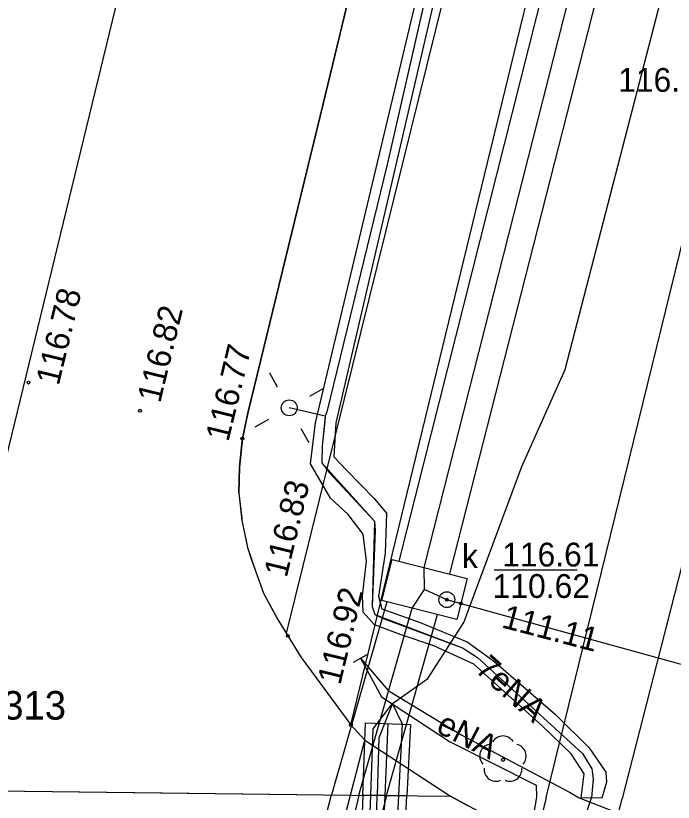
# Model space of a CAD drawing. Extents: x 6424617 to 6425697, y 5665845 to 5667190.
# Drawn here: x 6425408.09 to 6425428.81, y 5666563.12 to 5666587.89 of the extents above; entities that cross this region are included whole.
import ezdxf

# ---------------------------------------------------------------- set-up
doc = ezdxf.new("R2010")
doc.units = 0
for name, color, linetype in [('Warstwa 10', 7, 'Continuous'), ('Warstwa 11', 7, 'Continuous'), ('Warstwa 12', 7, 'Continuous'), ('Warstwa 13', 7, 'Continuous'), ('Warstwa 14', 7, 'Continuous'), ('Warstwa 15', 7, 'Continuous'), ('Warstwa 16', 7, 'Continuous'), ('Warstwa 2', 7, 'Continuous'), ('Warstwa 20', 7, 'Continuous'), ('Warstwa 25', 7, 'Continuous'), ('Warstwa 4', 7, 'Continuous'), ('Warstwa 5', 7, 'Continuous'), ('Warstwa 6', 7, 'Continuous'), ('Warstwa 61', 7, 'Continuous'), ('Warstwa 8', 7, 'Continuous'), ('Warstwa 9', 7, 'Continuous')]:
    doc.layers.add(name, color=color, linetype=linetype)

msp = doc.modelspace()

# ---------------------------------------------------------------- linework, layer by layer
at = {"layer": 'Warstwa 10'}
for points in [[(6425463.69, 5666713.42), (6425450.198, 5666658.334), (6425446.682, 5666643.647), (6425444.432, 5666634.297), (6425443.938, 5666632.196), (6425440.201, 5666616.58), (6425435.586, 5666597.316), (6425432.855, 5666585.915), (6425430.384, 5666576.151), (6425429.068, 5666570.528), (6425427.199, 5666563.24)], [(6425408.526, 5666486.136), (6425415.189, 5666513.682), (6425415.8, 5666514.595), (6425416.059, 5666515.322), (6425416.046, 5666515.972), (6425415.903, 5666516.524), (6425415.527, 5666516.858), (6425414.977, 5666516.815), (6425414.617, 5666516.009), (6425414.558, 5666515.29), (6425414.733, 5666514.858), (6425415.232, 5666514.782), (6425415.536, 5666515.098), (6425427.199, 5666563.24)]]:
    msp.add_lwpolyline(points, dxfattribs=at)
at = {"layer": 'Warstwa 11'}
msp.add_circle((6425423.441, 5666564.454), 0.05, dxfattribs=at)
for centre, start, end in [((6425423.441, 5666564.829), 30.1471, 149.8529), ((6425423.084, 5666564.57), 102.1471, 221.8529), ((6425423.798, 5666564.57), 318.1471, 77.8529), ((6425423.221, 5666564.151), 174.1471, 293.8529), ((6425423.661, 5666564.151), 246.1471, 5.8529)]:
    msp.add_arc(centre, 0.375, start, end, dxfattribs=at)
at = {"layer": 'Warstwa 12'}
for points in [[(6425429.948, 5666625.73), (6425423.857, 5666601.014), (6425423.825, 5666600.868), (6425423.805, 5666600.77), (6425423.785, 5666600.674), (6425419.792, 5666583.207), (6425417.89, 5666575.411), (6425417.843, 5666575.274), (6425417.83, 5666575.116), (6425417.74, 5666574.332), (6425417.734, 5666573.808), (6425417.958, 5666573.509), (6425419.396, 5666571.967), (6425419.414, 5666571.671), (6425419.317, 5666569.282), (6425419.405, 5666569.031), (6425419.7, 5666568.897), (6425422.168, 5666567.979), (6425422.642, 5666567.678), (6425425.95, 5666564.655), (6425426.241, 5666564.174), (6425426.282, 5666563.854), (6425426.235, 5666563.252)], [(6425419.959, 5666566.232), (6425421.072, 5666567.014), (6425422.209, 5666568.78), (6425424.038, 5666573.694), (6425425.402, 5666576.749), (6425429.473, 5666592.484), (6425433.587, 5666608.959), (6425433.509, 5666609.712), (6425433.806, 5666610.423), (6425435.93, 5666619.047)], [(6425432.007, 5666617.006), (6425426.287, 5666594.949), (6425420.155, 5666570.71)], [(6425421.765, 5666570.306), (6425427.85, 5666594.158), (6425433.674, 5666616.636)], [(6425424.798, 5666563.269), (6425430.321, 5666585.708), (6425436.792, 5666612.249), (6425437.109, 5666613.288)], [(6425417.843, 5666575.274), (6425416.706, 5666575.54)], [(6425441.217, 5666568.14), (6425439.239, 5666564.653), (6425421.672, 5666569.496), (6425420.968, 5666569.82)], [(6425419.785, 5666569.432), (6425418.038, 5666563.351)], [(6425419.768, 5666563.33), (6425421.383, 5666569.03)], [(6425418.947, 5666567.651), (6425419.614, 5666566.433), (6425421.76, 5666565.033), (6425424.489, 5666563.655), (6425424.494, 5666563.273)], [(6425418.947, 5666567.651), (6425419.822, 5666566.636), (6425422.142, 5666565.233), (6425425.539, 5666563.437), (6425425.841, 5666563.257)], [(6425419.277, 5666563.335), (6425419.354, 5666565.433), (6425419.959, 5666566.232)], [(6425419.959, 5666566.232), (6425419.526, 5666565.15), (6425419.478, 5666563.333)], [(6425420.158, 5666563.325), (6425420.274, 5666565.579), (6425419.959, 5666566.232)], [(6425407.053, 5666520.958), (6425418.038, 5666563.351)], [(6425419.768, 5666563.33), (6425408.806, 5666520.576)], [(6425419.239, 5666554.223), (6425418.943, 5666554.234), (6425419.277, 5666563.335)], [(6425419.239, 5666554.223), (6425419.478, 5666563.333)], [(6425419.239, 5666554.223), (6425419.689, 5666554.213), (6425420.158, 5666563.325)], [(6425424.798, 5666563.269), (6425407.429, 5666491.384), (6425382.182, 5666389.031), (6425381.68, 5666386.39)], [(6425424.494, 5666563.273), (6425422.467, 5666551.627), (6425413.972, 5666545.439), (6425413.323, 5666547.257)], [(6425414.219, 5666544.781), (6425422.911, 5666551.121), (6425426.036, 5666562.658), (6425426.235, 5666563.252)], [(6425425.841, 5666563.257), (6425426.893, 5666562.844), (6425427.082, 5666562.782), (6425427.381, 5666562.688), (6425427.779, 5666562.543), (6425429.234, 5666562.096)]]:
    msp.add_lwpolyline(points, dxfattribs=at)
at = {"layer": 'Warstwa 14'}
msp.add_lwpolyline([(6425425.777, 5666570.426), (6425423.161, 5666570.426)], dxfattribs=at)
for centre in [(6425421.672, 5666569.496), (6425422.114, 5666569.374)]:
    msp.add_circle(centre, 0.045, dxfattribs=at)
at = {"layer": 'Warstwa 16'}
msp.add_lwpolyline([(6425419.946, 5666570.763), (6425422.313, 5666570.168), (6425421.989, 5666568.877), (6425419.622, 5666569.473)], close=True, dxfattribs=at)
at = {"layer": 'Warstwa 2'}
msp.add_circle((6425416.706, 5666575.54), 0.25, dxfattribs=at)
at = {"layer": 'Warstwa 20'}
msp.add_line((6425418.729, 5666567.528), (6425419.165, 5666567.774), dxfattribs=at)
at = {"layer": 'Warstwa 25'}
for centre in [(6425408.486, 5666576.334), (6425412.001, 5666575.449), (6425415.23, 5666574.57), (6425416.66, 5666568.36), (6425418.65, 5666565.55)]:
    msp.add_circle(centre, 0.045, dxfattribs=at)
at = {"layer": 'Warstwa 4'}
for points in [[(6425416.337, 5666576.193), (6425416.091, 5666576.628)], [(6425417.359, 5666575.909), (6425417.794, 5666576.155)], [(6425416.053, 5666575.171), (6425415.618, 5666574.925)], [(6425417.075, 5666574.887), (6425417.321, 5666574.452)]]:
    msp.add_lwpolyline(points, dxfattribs=at)
msp.add_circle((6425421.672, 5666569.496), 0.25, dxfattribs=at)
at = {"layer": 'Warstwa 6'}
for points in [[(6425428.85, 5666619.55), (6425426.7, 5666617.43), (6425424.86, 5666613.84), (6425424.28, 5666611.91), (6425421.77, 5666601.61), (6425418.68, 5666588.86), (6425417.78, 5666585.11), (6425415.4, 5666575.37), (6425415.23, 5666574.57), (6425415.135, 5666573.675), (6425415.12, 5666572.85), (6425415.215, 5666571.993), (6425415.386, 5666571.143), (6425415.65, 5666570.37), (6425415.897, 5666569.705), (6425416.353, 5666568.851), (6425416.66, 5666568.36), (6425417.08, 5666567.68), (6425418.65, 5666565.55), (6425419.09, 5666565.07), (6425421.792, 5666563.306)], [(6425456.703, 5666531.501), (6425459.304, 5666543.782), (6425462.987, 5666543.257), (6425466.579, 5666542.746), (6425468.099, 5666550.832), (6425426.818, 5666561.105), (6425426.239, 5666561.299), (6425425.664, 5666561.506), (6425425.094, 5666561.725), (6425424.53, 5666561.957), (6425423.97, 5666562.202), (6425423.417, 5666562.46), (6425422.869, 5666562.73), (6425422.328, 5666563.012), (6425421.793, 5666563.306)]]:
    msp.add_lwpolyline(points, dxfattribs=at)
at = {"layer": 'Warstwa 61'}
for points in [[(6425475.759, 5666812.66), (6425466.898, 5666777.865), (6425461.33, 5666753.166), (6425457.929, 5666738.982), (6425455.155, 5666727.822), (6425448.977, 5666702.201), (6425442.987, 5666677.871), (6425436.476, 5666651.999), (6425429.948, 5666625.73), (6425423.857, 5666601.014), (6425419.792, 5666583.207), (6425417.89, 5666575.411), (6425417.843, 5666575.274), (6425417.74, 5666574.332), (6425417.734, 5666573.808), (6425419.396, 5666571.967), (6425419.317, 5666569.282), (6425419.405, 5666569.031), (6425422.168, 5666567.979), (6425422.642, 5666567.678), (6425425.95, 5666564.655), (6425426.241, 5666564.174), (6425426.282, 5666563.854), (6425426.235, 5666563.252)], [(6425418.903, 5666563.341), (6425418.966, 5666563.56), (6425420.584, 5666569.231), (6425420.968, 5666569.82), (6425420.96, 5666570.508), (6425427.069, 5666594.554), (6425432.841, 5666616.822), (6425433.006, 5666617.504), (6425433.184, 5666618.184), (6425440.898, 5666649.974), (6425444.447, 5666664.744)], [(6425419.817, 5666565.592), (6425419.717, 5666563.33)], [(6425418.903, 5666563.341), (6425418.852, 5666563.142), (6425407.93, 5666520.767), (6425407.753, 5666519.862), (6425407.572, 5666518.978), (6425396.839, 5666471.928), (6425396.703, 5666471.243), (6425396.496, 5666470.567), (6425385.286, 5666423.635), (6425385.173, 5666423.021)], [(6425419.717, 5666563.33), (6425419.316, 5666554.222)]]:
    msp.add_lwpolyline(points, dxfattribs=at)
at = {"layer": 'Warstwa 8'}
for p, q in [((6425405.241, 5666563.505), (6425419.26, 5666621.16)), ((6425417.78, 5666585.11), (6425418.68, 5666588.86)), ((6425415.4, 5666575.37), (6425417.78, 5666585.11)), ((6425415.23, 5666574.57), (6425415.4, 5666575.37)), ((6425415.135, 5666573.675), (6425415.222, 5666574.499)), ((6425415.222, 5666574.499), (6425415.23, 5666574.57)), ((6425415.12, 5666572.85), (6425415.135, 5666573.675)), ((6425415.12, 5666572.85), (6425415.207, 5666572.06)), ((6425415.207, 5666572.06), (6425415.215, 5666571.993)), ((6425415.215, 5666571.993), (6425415.345, 5666571.348)), ((6425415.345, 5666571.348), (6425415.387, 5666571.141)), ((6425415.387, 5666571.141), (6425415.508, 5666570.787)), ((6425415.508, 5666570.787), (6425415.65, 5666570.37)), ((6425415.65, 5666570.37), (6425415.897, 5666569.705)), ((6425415.897, 5666569.705), (6425416.334, 5666568.885)), ((6425416.334, 5666568.885), (6425416.353, 5666568.851)), ((6425416.353, 5666568.851), (6425416.66, 5666568.36)), ((6425416.66, 5666568.36), (6425417.08, 5666567.68)), ((6425417.08, 5666567.68), (6425418.65, 5666565.55)), ((6425418.65, 5666565.55), (6425419.09, 5666565.07)), ((6425418.634, 5666563.343), (6425419.09, 5666565.07)), ((6425419.09, 5666565.07), (6425421.792, 5666563.306)), ((6425419.09, 5666565.07), (6425421.792, 5666563.306)), ((6425405.241, 5666563.505), (6425418.634, 5666563.343)), ((6425405.241, 5666563.505), (6425412.697, 5666563.415)), ((6425412.697, 5666563.415), (6425418.634, 5666563.343)), ((6425416.52, 5666555.34), (6425418.634, 5666563.343)), ((6425416.52, 5666555.34), (6425418.634, 5666563.343)), ((6425418.634, 5666563.343), (6425421.793, 5666563.306)), ((6425418.634, 5666563.343), (6425421.792, 5666563.306)), ((6425418.634, 5666563.343), (6425421.792, 5666563.306)), ((6425421.793, 5666563.306), (6425422.328, 5666563.012))]:
    msp.add_line(p, q, dxfattribs=at)
for points in [[(6425421.644, 5666589.979), (6425418.176, 5666575.063), (6425418.107, 5666573.992), (6425418.524, 5666573.564), (6425419.386, 5666572.681), (6425419.775, 5666572.225), (6425419.732, 5666570.958), (6425419.518, 5666569.608), (6425419.627, 5666569.212), (6425420.833, 5666568.775), (6425422.317, 5666568.165), (6425423.147, 5666567.571), (6425425.098, 5666565.885), (6425426.155, 5666564.83), (6425426.681, 5666564.063), (6425426.706, 5666563.752), (6425426.558, 5666563.248), (6425425.911, 5666563.256), (6425426.005, 5666564.015), (6425425.59, 5666564.64), (6425424.672, 5666565.524), (6425422.527, 5666567.466), (6425421.267, 5666568.044), (6425420.236, 5666568.388), (6425419.396, 5666568.708), (6425419.034, 5666569.106), (6425419.011, 5666569.614), (6425419.138, 5666570.711), (6425419.035, 5666571.558), (6425418.564, 5666572.184), (6425418.008, 5666572.698), (6425417.372, 5666573.775), (6425417.529, 5666575.071), (6425421.289, 5666590.857)], [(6425419.026, 5666563.338), (6425418.693, 5666554.243), (6425419.939, 5666554.2), (6425420.408, 5666563.322)]]:
    msp.add_lwpolyline(points, dxfattribs=at)
msp.add_lwpolyline([(6425420.408, 5666563.322), (6425419.026, 5666563.338), (6425419.11, 5666565.618), (6425420.524, 5666565.566)], close=True, dxfattribs=at)
at = {"layer": 'Warstwa 9'}
for p, q in [((6425424.08, 5666587.87), (6425432.48, 5666622.25)), ((6425416.62, 5666568.44), (6425421.58, 5666588.48)), ((6425418.65, 5666565.55), (6425424.08, 5666587.87)), ((6425416.62, 5666568.44), (6425416.66, 5666568.36)), ((6425416.66, 5666568.36), (6425417.08, 5666567.68)), ((6425417.08, 5666567.68), (6425418.65, 5666565.55))]:
    msp.add_line(p, q, dxfattribs=at)

# ---------------------------------------------------------------- texts
at = {"layer": 'Warstwa 13'}
for s, rotation, p in [('7eNA', 318.2723, (6425422.529, 5666567.257)), ('eNA', 332.8197, (6425421.295, 5666565.344))]:
    msp.add_text(s, height=0.75, rotation=rotation, dxfattribs=at).set_placement(p)
at = {"layer": 'Warstwa 14'}
msp.add_text('110.62', height=0.75, dxfattribs=at).set_placement((6425423.117, 5666569.552))
msp.add_text('111.11', height=0.75, rotation=345.2758, dxfattribs=at).set_placement((6425423.368, 5666568.629))
at = {"layer": 'Warstwa 15'}
for s, p in [('116.84', (6425427.072, 5666585.492)), ('116.61', (6425423.416, 5666570.542))]:
    msp.add_text(s, height=0.75, dxfattribs=at).set_placement(p)
at = {"layer": 'Warstwa 25'}
for s, rotation, p in [('116.78', 76.3352, (6425409.439, 5666576.216)), ('116.82', 76.3352, (6425412.637, 5666575.667)), ('116.77', 76.2664, (6425414.786, 5666574.444)), ('116.83', 76.2607, (6425416.624, 5666570.168)), ('116.92', 76.3294, (6425418.313, 5666566.786))]:
    msp.add_text(s, height=0.75, rotation=rotation, dxfattribs=at).set_placement(p)
at = {"layer": 'Warstwa 4'}
msp.add_text('1313', height=0.9, dxfattribs=at).set_placement((6425406.993, 5666565.72))
at = {"layer": 'Warstwa 5'}
msp.add_text('k', height=0.75, dxfattribs=at).set_placement((6425422.15, 5666570.492))

doc.saveas('drawing.dxf')
